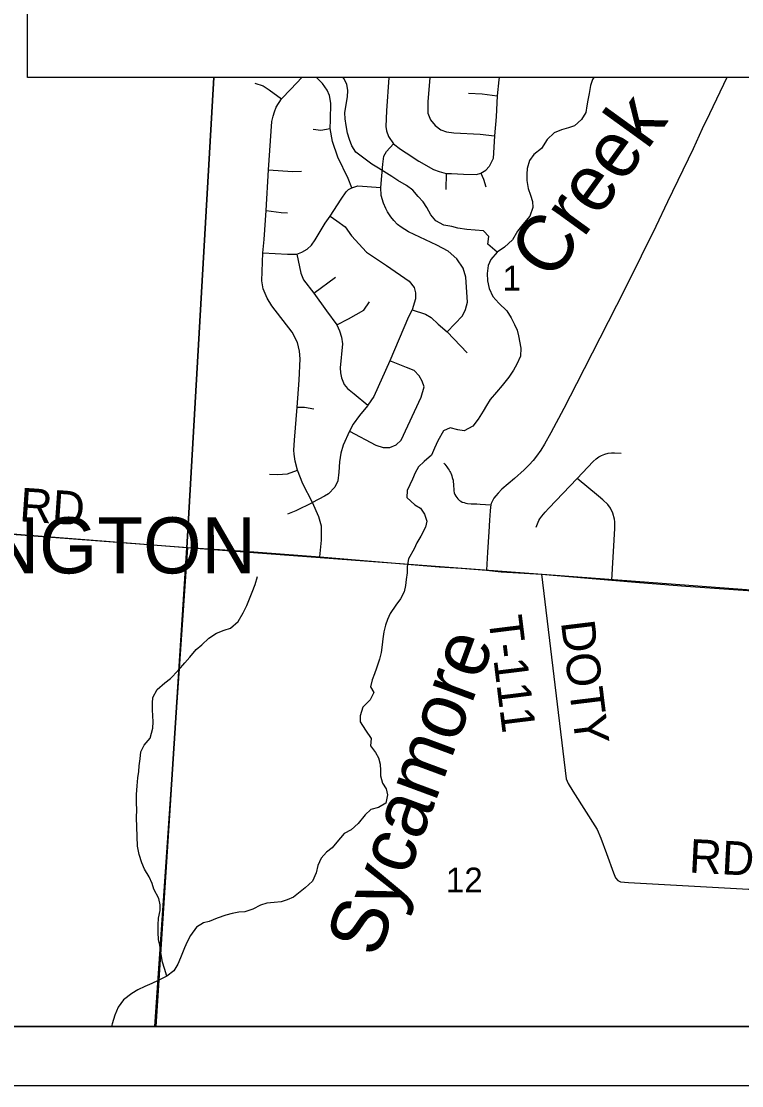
# Model space of a CAD drawing. Extents: x 0 to 34, y 0 to 26.1.
# Drawn here: x 28.299 to 29.516, y 14 to 15.797 of the extents above; entities that cross this region are included whole.
import ezdxf

# ---------------------------------------------------------------- set-up
doc = ezdxf.new("R2010")
doc.units = 0
for name, color, linetype in [('GM_X_Corporation_Text', 7, 'Continuous'), ('GM_X_Minor_River', 7, 'Continuous'), ('GM_X_Minor_River_Text', 7, 'Continuous'), ('GM_X_Section', 7, 'Continuous'), ('GM_X_Section_Text', 7, 'Continuous'), ('GM_X_Township_Road', 7, 'Continuous'), ('GM_X_Township_Road_Text', 7, 'Continuous'), ('SH_Data', 7, 'Continuous')]:
    doc.layers.add(name, color=color, linetype=linetype)

msp = doc.modelspace()

# ---------------------------------------------------------------- linework, layer by layer
at = {"layer": 'GM_X_Minor_River'}
for points in [[(29.1027, 15.4075), (29.0873, 15.4209), (29.0886, 15.4338), (29.0796, 15.4438), (29.0659, 15.4447), (29.0519, 15.446), (29.0364, 15.448), (29.0262, 15.4508), (29.0126, 15.4532), (28.9991, 15.4602), (28.9908, 15.4705), (28.9838, 15.4827), (28.9778, 15.4923), (28.9692, 15.5018), (28.9606, 15.5122), (28.9497, 15.5199), (28.935, 15.5284), (28.9252, 15.5353), (28.9027, 15.5492), (28.891, 15.5562), (28.8775, 15.5662), (28.8643, 15.5766), (28.8576, 15.5869), (28.8536, 15.5976), (28.8499, 15.6086), (28.8478, 15.6215), (28.8464, 15.6329), (28.8457, 15.6428), (28.8478, 15.6568), (28.8502, 15.6701), (28.8507, 15.6803), (28.8489, 15.6913), (28.8441, 15.7009), (28.843, 15.7025)], [(29.2661, 15.7025), (29.2638, 15.6992), (29.2603, 15.689), (29.2582, 15.6753), (29.2558, 15.6643), (29.2546, 15.6545), (29.2526, 15.6435), (29.2456, 15.6314), (29.2334, 15.6209), (29.2235, 15.6176), (29.2117, 15.6139), (29.1992, 15.6091), (29.1873, 15.5979), (29.1777, 15.5828), (29.1647, 15.5727), (29.1574, 15.5621), (29.1538, 15.5489), (29.153, 15.5394), (29.1532, 15.5284), (29.1553, 15.5151), (29.1594, 15.5037), (29.1627, 15.493), (29.1633, 15.4831), (29.1579, 15.4684), (29.1464, 15.4545), (29.1371, 15.4428), (29.1287, 15.4285), (29.1153, 15.4161), (29.1027, 15.4075), (29.0923, 15.3951), (29.0877, 15.3849), (29.086, 15.3716), (29.0866, 15.3591), (29.0895, 15.3461), (29.0958, 15.3324), (29.1059, 15.3217), (29.119, 15.3086), (29.1265, 15.2968), (29.1324, 15.2853), (29.1365, 15.2758), (29.1387, 15.2663), (29.1426, 15.2454), (29.1421, 15.2321), (29.1362, 15.2185), (29.1305, 15.2083), (29.1227, 15.1966), (29.1112, 15.1823), (29.102, 15.1714), (29.0913, 15.159), (29.0847, 15.1488), (29.0793, 15.139), (29.0705, 15.1258), (29.062, 15.1138), (29.0471, 15.1056), (29.0362, 15.1076), (29.0237, 15.1108), (29.0123, 15.1056), (29.0026, 15.089), (28.9972, 15.0765), (28.9922, 15.0648), (28.9795, 15.0539), (28.97, 15.0449)], [(28.97, 15.0449), (28.9646, 15.0351), (28.9599, 15.0245), (28.9556, 15.0147), (28.951, 15.0049), (28.9501, 14.9935), (28.9636, 14.9808), (28.9734, 14.975), (28.9801, 14.9651), (28.9838, 14.9533), (28.9821, 14.9434), (28.974, 14.928), (28.9671, 14.9167), (28.9628, 14.9068), (28.9531, 14.8895), (28.9511, 14.8766), (28.9506, 14.8663), (28.9494, 14.855), (28.9481, 14.8444), (28.9457, 14.8338), (28.9395, 14.8221), (28.9315, 14.8115), (28.9222, 14.7972), (28.9176, 14.7874), (28.9141, 14.7775), (28.9117, 14.7662), (28.9096, 14.7544), (28.9088, 14.7442), (28.9071, 14.7313), (28.904, 14.7203), (28.8989, 14.7052), (28.8954, 14.6954), (28.8915, 14.6856), (28.8891, 14.6734), (28.8943, 14.6639), (28.8885, 14.6514), (28.8762, 14.639), (28.8715, 14.6247), (28.8714, 14.6144), (28.8807, 14.6003), (28.89, 14.5865), (28.8888, 14.574), (28.8973, 14.5629), (28.9025, 14.5534), (28.9051, 14.5431), (28.9057, 14.5325), (28.906, 14.523), (28.9093, 14.5108), (28.9156, 14.5012), (28.9178, 14.4913), (28.9146, 14.4773), (28.9024, 14.4699), (28.8895, 14.4662), (28.8799, 14.4572), (28.868, 14.4429), (28.8565, 14.432), (28.8447, 14.4257), (28.8321, 14.4114), (28.824, 14.4016), (28.8145, 14.3941), (28.8056, 14.384), (28.8002, 14.3719), (28.7974, 14.3594), (28.7908, 14.3454), (28.7786, 14.3342), (28.7587, 14.3184), (28.7481, 14.3136), (28.7378, 14.3103), (28.7264, 14.3093), (28.7139, 14.3083), (28.7033, 14.3046), (28.6899, 14.2983), (28.6766, 14.2935), (28.6664, 14.2928), (28.655, 14.291), (28.6444, 14.2881), (28.6299, 14.283), (28.6162, 14.2774), (28.6067, 14.2749), (28.5953, 14.2678), (28.5849, 14.2538), (28.5791, 14.2429), (28.5748, 14.2327), (28.5682, 14.216), (28.5635, 14.2051), (28.557, 14.1942), (28.5448, 14.1848), (28.5303, 14.1777), (28.5196, 14.1725), (28.5078, 14.1677), (28.4957, 14.1618), (28.4857, 14.1558), (28.4716, 14.1449), (28.4628, 14.1325), (28.4569, 14.1193), (28.4526, 14.1045), (28.4513, 14.1)], [(28.5448, 14.1848), (28.5407, 14.1981), (28.5378, 14.2084), (28.5353, 14.2213), (28.5332, 14.2373), (28.531, 14.2468), (28.5304, 14.2586), (28.5305, 14.2715), (28.5311, 14.2832), (28.5335, 14.2957), (28.5339, 14.3056), (28.5314, 14.3162), (28.5232, 14.3319), (28.5199, 14.3414), (28.5151, 14.3528), (28.5073, 14.3655), (28.5025, 14.3761), (28.4981, 14.3906), (28.4956, 14.4047), (28.495, 14.421), (28.4941, 14.4373), (28.4939, 14.4521), (28.494, 14.4662), (28.4937, 14.4772), (28.4939, 14.492), (28.4948, 14.5064), (28.4961, 14.5197), (28.4974, 14.5306), (28.4982, 14.5401), (28.4999, 14.5519), (28.5011, 14.5636), (28.5065, 14.5753), (28.5165, 14.5866), (28.5212, 14.6036), (28.5217, 14.6146), (28.5215, 14.6245), (28.5208, 14.6348), (28.5206, 14.6458), (28.5214, 14.6553), (28.5288, 14.6688), (28.5418, 14.6805), (28.5513, 14.6876), (28.5643, 14.7011), (28.5751, 14.7139), (28.5835, 14.7237), (28.5947, 14.7365), (28.6042, 14.7447), (28.6157, 14.756), (28.6287, 14.7642), (28.6416, 14.769), (28.6522, 14.7727), (28.6652, 14.7839), (28.6741, 14.7986), (28.6799, 14.8107), (28.6846, 14.8224), (28.6893, 14.8334), (28.6939, 14.8463), (28.6979, 14.8599)]]:
    msp.add_lwpolyline(points, dxfattribs=at)
at = {"layer": 'GM_X_Section'}
for points in [[(28.6244, 15.7025), (28.5788, 14.9085), (27.5444, 14.9891), (27.6154, 15.9857), (28.1277, 15.9466), (28.3097, 15.9346)], [(29.6421, 15.7025), (29.5845, 14.8326), (28.5788, 14.9085), (28.6244, 15.7025)]]:
    msp.add_lwpolyline(points, dxfattribs=at)
for points in [[(27.4819, 14.1), (28.5264, 14.1), (28.5788, 14.9085), (27.5444, 14.9891)], [(28.5264, 14.1), (29.5379, 14.1), (29.5829, 14.814), (29.5845, 14.8326), (28.5788, 14.9085)]]:
    msp.add_lwpolyline(points, close=True, dxfattribs=at)
at = {"layer": 'GM_X_Township_Road'}
for p, q in [((29.017, 15.5406), (29.0164, 15.5136)), ((28.7932, 15.3384), (28.8297, 15.3652)), ((28.5246, 14.1), (28.5805, 14.9091))]:
    msp.add_line(p, q, dxfattribs=at)
for points in [[(28.6938, 15.6928), (28.7075, 15.6886), (28.718, 15.6816), (28.7387, 15.6666)], [(28.8034, 14.8928), (28.8061, 14.9213), (28.8059, 14.9449), (28.8019, 14.9606), (28.7907, 14.9849), (28.7749, 15.0162), (28.7655, 15.0397), (28.7615, 15.0547), (28.76, 15.0663), (28.7596, 15.0734), (28.7604, 15.0903), (28.765, 15.1456), (28.7684, 15.1912), (28.7701, 15.2273), (28.7689, 15.2406), (28.7656, 15.2549), (28.7568, 15.2725), (28.7225, 15.317), (28.7142, 15.3301), (28.7076, 15.3457), (28.7051, 15.3594), (28.7072, 15.4065), (28.7092, 15.4291), (28.7129, 15.4778), (28.7169, 15.5467), (28.7224, 15.6281), (28.7246, 15.6371), (28.7265, 15.6443), (28.7298, 15.6522), (28.7387, 15.6666), (28.7545, 15.6827), (28.7729, 15.7025)], [(28.8574, 15.5163), (28.8512, 15.5319), (28.834, 15.5679), (28.8245, 15.5943), (28.8208, 15.6162), (28.8212, 15.631), (28.8221, 15.6594), (28.8199, 15.672), (28.816, 15.681), (28.8079, 15.6925), (28.7978, 15.7025)], [(28.92, 15.7025), (28.9158, 15.6462), (28.9146, 15.62), (28.9161, 15.6124), (28.9192, 15.603), (28.9275, 15.5904)], [(28.989, 15.7025), (28.9879, 15.6882), (28.9857, 15.662), (28.9857, 15.6501), (28.9857, 15.6421), (28.9904, 15.631), (28.9984, 15.6217), (29.0079, 15.6143), (29.0175, 15.6109), (29.0295, 15.609), (29.0739, 15.6066), (29.0981, 15.6042)], [(29.4909, 15.7025), (29.4613, 15.641), (29.4494, 15.6159), (29.4338, 15.5821), (29.3907, 15.4927), (29.3707, 15.4508), (29.3463, 15.4007), (29.3186, 15.3452), (29.2764, 15.2622), (29.2366, 15.185), (29.2154, 15.1436), (29.1938, 15.1024), (29.1831, 15.0835), (29.1764, 15.073), (29.1691, 15.0629), (29.1634, 15.0556), (29.1571, 15.0486), (29.1482, 15.0399), (29.1319, 15.0255), (29.111, 15.0071), (29.1044, 15.0006), (29.1005, 14.9959), (29.0975, 14.992), (29.0955, 14.9888), (29.0938, 14.9855), (29.093, 14.983), (29.0924, 14.9811), (29.0914, 14.9769), (29.0908, 14.9708), (29.09, 14.9549), (29.0888, 14.9354), (29.0866, 14.9012), (29.0847, 14.8704)], [(29.1061, 15.7025), (29.1059, 15.6984), (29.1031, 15.6715), (29.1012, 15.6363), (29.0981, 15.6042), (29.0959, 15.5658), (29.0894, 15.552)], [(29.0545, 15.6763), (29.0777, 15.6749), (29.1031, 15.6715)], [(28.7923, 15.6153), (28.8051, 15.6137), (28.8208, 15.6162)], [(29.0185, 15.2729), (29.0443, 15.3001), (29.0496, 15.3108), (29.0526, 15.323), (29.0501, 15.3654), (29.0453, 15.3805), (29.035, 15.3961), (29.0199, 15.4093), (29.0012, 15.4191), (28.9529, 15.4417), (28.941, 15.4495), (28.9344, 15.4541), (28.9281, 15.461), (28.9232, 15.4671), (28.9178, 15.4756), (28.9147, 15.4814), (28.911, 15.49), (28.9071, 15.5034), (28.9064, 15.517), (28.9095, 15.556), (28.9116, 15.5695), (28.9159, 15.5778), (28.9275, 15.5904)], [(28.9275, 15.5904), (28.9396, 15.5812), (28.9489, 15.575), (28.9703, 15.5612), (28.9952, 15.547), (29.005, 15.5435), (29.017, 15.5406), (29.0255, 15.5402), (29.0459, 15.539), (29.0682, 15.5387), (29.0754, 15.5407), (29.0839, 15.5458), (29.0894, 15.552)], [(28.7169, 15.5467), (28.7571, 15.5438), (28.7726, 15.5441)], [(29.0754, 15.5407), (29.08, 15.5309), (29.0837, 15.5176)], [(28.7072, 15.4065), (28.7281, 15.4055), (28.7487, 15.404), (28.7647, 15.4042), (28.7728, 15.4075), (28.7819, 15.4125), (28.789, 15.4194), (28.7954, 15.4285), (28.8123, 15.4565), (28.8208, 15.4684), (28.8391, 15.497), (28.8478, 15.5092), (28.8518, 15.5131), (28.8574, 15.5163), (28.8673, 15.5193), (28.9064, 15.517)], [(28.7129, 15.4778), (28.7379, 15.4746), (28.7488, 15.474)], [(28.8208, 15.4684), (28.8323, 15.4605), (28.8459, 15.4505), (28.8569, 15.4354), (28.882, 15.4078), (28.9161, 15.3849), (28.9543, 15.3586), (28.9624, 15.3477), (28.9651, 15.339), (28.9648, 15.3286), (28.9594, 15.3099), (28.959, 15.309)], [(28.7647, 15.4042), (28.7714, 15.3721), (28.776, 15.3611), (28.7932, 15.3384), (28.8144, 15.3087), (28.8322, 15.2849), (28.8365, 15.2749), (28.8401, 15.264), (28.8415, 15.2528), (28.8377, 15.2123), (28.838, 15.2037), (28.8401, 15.1952), (28.8446, 15.1842), (28.8498, 15.1776), (28.8615, 15.1682), (28.8847, 15.1489)], [(28.8322, 15.2849), (28.8515, 15.2947), (28.8777, 15.3097), (28.8874, 15.3235)], [(28.959, 15.309), (28.9529, 15.2981), (28.9215, 15.224), (28.8945, 15.164), (28.8847, 15.1489), (28.8841, 15.1482)], [(28.9594, 15.3099), (28.9818, 15.3029), (28.9914, 15.297), (29.0034, 15.2862), (29.0185, 15.2729), (29.0523, 15.2377)], [(28.8536, 15.105), (28.8977, 15.0815), (28.9101, 15.0776), (28.9214, 15.0778), (28.932, 15.0824), (28.941, 15.0903), (28.9745, 15.1628), (28.9793, 15.1802), (28.9762, 15.1897), (28.971, 15.1987), (28.9624, 15.2078), (28.9498, 15.213), (28.9215, 15.224)], [(28.765, 15.1456), (28.7774, 15.1456), (28.7933, 15.1429)], [(28.8841, 15.1482), (28.8703, 15.1318), (28.8596, 15.1171), (28.8536, 15.105), (28.8427, 15.0817), (28.8389, 15.0679), (28.8364, 15.0533), (28.8354, 15.0358), (28.8337, 15.0214), (28.8289, 15.0109), (28.8181, 14.9995), (28.8114, 14.9955), (28.7907, 14.9849)], [(29.2378, 15.0251), (29.265, 15.0541), (29.2703, 15.0587), (29.2747, 15.0617), (29.2792, 15.0642), (29.2845, 15.0665), (29.2902, 15.0679), (29.2962, 15.0689), (29.3009, 15.0689), (29.3125, 15.0683)], [(29.0129, 15.0514), (29.0142, 15.0496), (29.0181, 15.0448), (29.0203, 15.0419), (29.0218, 15.0395), (29.0232, 15.0369), (29.0238, 15.0356), (29.0244, 15.0343), (29.0257, 15.0315), (29.0264, 15.0297), (29.0271, 15.0273), (29.0277, 15.0255), (29.0283, 15.0227), (29.0287, 15.0197), (29.029, 15.016), (29.0292, 15.0124), (29.0295, 15.008), (29.0297, 15.0063), (29.0299, 15.0044), (29.0305, 15.0014), (29.0315, 14.9985), (29.0329, 14.9957), (29.0346, 14.9932), (29.0365, 14.9908), (29.0375, 14.9898), (29.039, 14.9884), (29.0413, 14.987), (29.044, 14.9856), (29.0469, 14.9847), (29.0499, 14.9839), (29.0529, 14.9834), (29.059, 14.9827), (29.0685, 14.9823), (29.0743, 14.982), (29.0924, 14.9811)], [(28.7186, 15.0326), (28.7317, 15.0322), (28.7486, 15.0333), (28.7655, 15.0397)], [(29.1686, 14.9433), (29.1734, 14.9544), (29.1751, 14.9573), (29.1782, 14.9618), (29.1809, 14.9651), (29.1841, 14.9686), (29.1903, 14.9751), (29.2378, 15.0251)], [(29.2964, 14.8537), (29.3016, 14.9409), (29.3018, 14.9522), (29.3011, 14.9569), (29.2981, 14.9667), (29.2943, 14.9755), (29.2898, 14.9815), (29.2813, 14.9895), (29.2742, 14.9953), (29.2378, 15.0251)], [(28.7494, 14.9658), (28.7632, 14.9714), (28.7907, 14.9849)], [(27.703, 14.9701), (27.9698, 14.9541), (28.1567, 14.9408), (28.5805, 14.9091)], [(28.5805, 14.9091), (28.6692, 14.9031), (28.8034, 14.8928), (29.0051, 14.8762), (29.0422, 14.874), (29.0847, 14.8704)], [(29.0847, 14.8704), (29.1096, 14.868), (29.1775, 14.8637), (29.2964, 14.8537), (29.3433, 14.8498), (29.4214, 14.8437), (29.5263, 14.8362), (29.5703, 14.833), (29.5829, 14.8315), (29.585, 14.8304), (29.5866, 14.8251), (29.5872, 14.8147), (29.594, 14.809), (29.5968, 14.809), (29.5978, 14.8089)], [(29.1775, 14.8637), (29.2196, 14.5184), (29.2229, 14.5101), (29.2305, 14.4971), (29.2718, 14.4328), (29.2781, 14.418), (29.2874, 14.392), (29.2991, 14.3593), (29.3028, 14.3511), (29.3067, 14.3463), (29.3113, 14.3442), (29.3247, 14.3431), (29.5276, 14.332), (29.5368, 14.3317), (29.5434, 14.331), (29.5487, 14.3287), (29.5518, 14.3259)]]:
    msp.add_lwpolyline(points, dxfattribs=at)
at = {"layer": 'SH_Data'}
for points in [[(23.4167, 21), (30.4167, 21), (30.4167, 14), (23.4167, 14)], [(23.5167, 20.9), (30.3167, 20.9), (30.3167, 14.1), (23.5167, 14.1)], [(28.3097, 16.5425), (29.9598, 16.5425), (29.9598, 15.7025), (28.3097, 15.7025)]]:
    msp.add_lwpolyline(points, close=True, dxfattribs=at)

# ---------------------------------------------------------------- texts
at = {"layer": 'GM_X_Corporation_Text'}
msp.add_text('PICKERINGTON', height=0.094697, rotation=0, dxfattribs=at).set_placement((27.731, 14.8651))
at = {"layer": 'GM_X_Minor_River_Text'}
for s, height, rotation, p in [('Creek', 0.0947, 54.088, (29.1948, 15.3561)), ('Sycamore', 0.09469, 69.6704, (28.9005, 14.2137))]:
    msp.add_text(s, height=height, rotation=rotation, dxfattribs=at).set_placement(p)
at = {"layer": 'GM_X_Section_Text'}
for s, height, p in [('1', 0.0419, (29.1121, 15.3428)), ('12', 0.04186, (29.0162, 14.3264))]:
    msp.add_text(s, height=height, rotation=0, dxfattribs=at).set_placement(p)
at = {"layer": 'GM_X_Township_Road_Text'}
for s, rotation, p in [('RD', 356.055, (28.2949, 14.9533)), ('T-111', 277.0202, (29.0879, 14.7907)), ('DOTY', 276.971, (29.2105, 14.7829)), ('RD', 357.0388, (29.4261, 14.36))]:
    msp.add_text(s, height=0.05682, rotation=rotation, dxfattribs=at).set_placement(p)

doc.saveas('drawing.dxf')
